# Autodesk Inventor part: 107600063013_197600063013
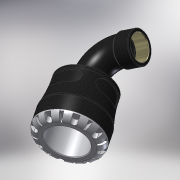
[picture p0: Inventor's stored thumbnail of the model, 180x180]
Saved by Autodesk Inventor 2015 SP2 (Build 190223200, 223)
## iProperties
Created: 2016-12
Part Number: 107600063013_197600063013
Material: PVC-Piping
Description: PLASSON 90° ELBOW WITH FEMALE INTEGRAL BRASS 63X1.1/4" SERIES 1
Document SubType Name: Modeling
Designer: KIM
Mass: 664.223 g
Surface Area: 733.008 cm^2
Volume: 474.445 cm^3
Density: 1.4 g/cm^3
Appearance: Black Cast
Author: KIM
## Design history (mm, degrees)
derived "1076.ipt"
feature "Solid1::1076.ipt"
tag "TaggingFeature1"
body "Solid1"
other parameters: "d1" = 37.8, "d2" = 63, "d3" = 78.75, "d4" = 103, "d8" = 90.64, "d13" = 9.7, "d14" = 9.7, "d15" = 0, "d17" = 360 deg, "d19" = 8 deg, "d20" = 1.26, "d21" = 1.26, "d22" = 8 deg, "d24" = 0, "d26" = 360 deg, "d33" = 10.3, "d51" = 1.03, "d54" = 22.05, "d55" = 13.86, "d57" = 19.012, "d58" = 0, "d74" = 0, "d82" = 1.26, "d115" = 360 deg, "d207" = 90 deg, "d228" = 18.7425, "d248" = 5.4, "d270" = 143, "d279" = 68, "d281" = 5.8428, "d294" = 38.952, "d295" = 21, "d296" = 23.1, "d297" = 35.0568, "d299" = 45.57384, "d300" = 35.0568, "d301" = 0, "d302" = 0, "d306" = 2.53188, "d309" = 90.9, "d310" = 22.53308, "d312" = 15 deg, "d313" = 0.824, "d314" = 10.26, "d315" = 0.515, "d_" = 63, "E_" = 103, "A_" = 143, "A_1" = 68, "l_2" = 21, "Rp_" = 38.952, "d9" = 12.125, "d11" = 103, "d12" = 78.75, "d298" = 50.6376
